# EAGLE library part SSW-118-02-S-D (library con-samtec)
THROUGH-HOLE .025" SQ POST SOCKET Source: Samtec SSW.pdf
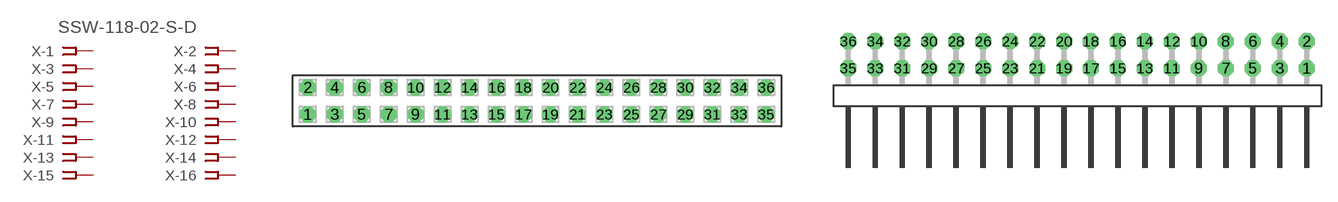
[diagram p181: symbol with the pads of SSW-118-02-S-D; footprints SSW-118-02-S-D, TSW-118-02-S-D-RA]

Designator prefix X; gates -1=FPINV -2=FPIN -3=FPIN -4=FPIN -5=FPIN -6=FPIN -7=FPIN -8=FPIN -9=FPIN -10=FPIN -11=FPIN -12=FPIN -13=FPIN -14=FPIN -15=FPIN -16=FPIN -17=FPIN -18=FPIN -19=FPIN -20=FPIN -21=FPIN -22=FPIN -23=FPIN -24=FPIN -25=FPIN -26=FPIN -27=FPIN -28=FPIN -29=FPIN -30=FPIN -31=FPIN -32=FPIN -33=FPIN -34=FPIN -35=FPIN -36=FPIN

## SSW-118-02-S-D (MPN: SSW-118-02-S-D; OC_FARNELL: unknown; OC_NEWARK: 11P9606)  [SSW-118-02-S-D]
1  -1:1  pas
2  -2:1  pas
3  -3:1  pas
4  -4:1  pas
5  -5:1  pas
6  -6:1  pas
7  -7:1  pas
8  -8:1  pas
9  -9:1  pas
10  -10:1  pas
11  -11:1  pas
12  -12:1  pas
13  -13:1  pas
14  -14:1  pas
15  -15:1  pas
16  -16:1  pas
17  -17:1  pas
18  -18:1  pas
19  -19:1  pas
20  -20:1  pas
21  -21:1  pas
22  -22:1  pas
23  -23:1  pas
24  -24:1  pas
25  -25:1  pas
26  -26:1  pas
27  -27:1  pas
28  -28:1  pas
29  -29:1  pas
30  -30:1  pas
31  -31:1  pas
32  -32:1  pas
33  -33:1  pas
34  -34:1  pas
35  -35:1  pas
36  -36:1  pas

## SSW-118-02-S-D-RA (MPN: SSW-118-02-S-D-RA; OC_FARNELL: unknown; OC_NEWARK: 11P9607)  [TSW-118-02-S-D-RA]
Pads as for SSW-118-02-S-D

## Footprint SSW-118-02-S-D (pad centres in mm)
THROUGH-HOLE .025" SQ POST SOCKET Source: Samtec SSW.pdf
drill 1 pad 1.5 octagon: 1 -21.59,-1.27; 2 -21.59,1.27; 3 -19.05,-1.27; 4 -19.05,1.27; 5 -16.51,-1.27; 6 -16.51,1.27; 7 -13.97,-1.27; 8 -13.97,1.27; 9 -11.43,-1.27; 10 -11.43,1.27; 11 -8.89,-1.27; 12 -8.89,1.27; 13 -6.35,-1.27; 14 -6.35,1.27; 15 -3.81,-1.27; 16 -3.81,1.27; 17 -1.27,-1.27; 18 -1.27,1.27; 19 1.27,-1.27; 20 1.27,1.27; 21 3.81,-1.27; 22 3.81,1.27; 23 6.35,-1.27; 24 6.35,1.27; 25 8.89,-1.27; 26 8.89,1.27; 27 11.43,-1.27; 28 11.43,1.27; 29 13.97,-1.27; 30 13.97,1.27; 31 16.51,-1.27; 32 16.51,1.27; 33 19.05,-1.27; 34 19.05,1.27; 35 21.59,-1.27; 36 21.59,1.27

## Footprint TSW-118-02-S-D-RA (pad centres in mm)
THROUGH-HOLE .025" SQ POST HEADER Source: Samtec TSW.pdf
drill 1 pad 1.5 octagon: 1 21.59,1.524; 2 21.59,4.064; 3 19.05,1.524; 4 19.05,4.064; 5 16.51,1.524; 6 16.51,4.064; 7 13.97,1.524; 8 13.97,4.064; 9 11.43,1.524; 10 11.43,4.064; 11 8.89,1.524; 12 8.89,4.064; 13 6.35,1.524; 14 6.35,4.064; 15 3.81,1.524; 16 3.81,4.064; 17 1.27,1.524; 18 1.27,4.064; 19 -1.27,1.524; 20 -1.27,4.064; 21 -3.81,1.524; 22 -3.81,4.064; 23 -6.35,1.524; 24 -6.35,4.064; 25 -8.89,1.524; 26 -8.89,4.064; 27 -11.43,1.524; 28 -11.43,4.064; 29 -13.97,1.524; 30 -13.97,4.064; 31 -16.51,1.524; 32 -16.51,4.064; 33 -19.05,1.524; 34 -19.05,4.064; 35 -21.59,1.524; 36 -21.59,4.064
